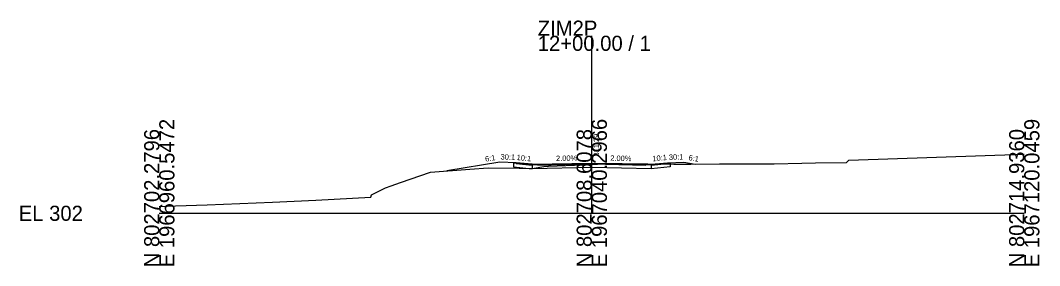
# Model space of a CAD drawing. Extents: x 1950845 to 1951408, y 736831 to 740365.
# Drawn here: x 1950844.5 to 1951033.1, y 738831.5 to 738876.9 of the extents above; entities that cross this region are included whole.
import ezdxf

# ---------------------------------------------------------------- set-up
doc = ezdxf.new("R2010")
doc.units = 0
for name, color, linetype in [('RD_GPK_XS_Cell', 7, 'Continuous'), ('RD_XS_Base', 7, 'Continuous'), ('RD_XS_EarthShd', 7, 'Continuous'), ('RD_XS_ExGround', 7, 'Continuous'), ('RD_XS_Pave', 7, 'Continuous'), ('RD_XS_PaveOvlay', 7, 'Continuous'), ('RD_XS_TieSlope', 7, 'Continuous'), ('RD_XS_TX_Elev_PR', 7, 'Continuous'), ('RD_XS_TX_Slope', 7, 'Continuous')]:
    doc.layers.add(name, color=color, linetype=linetype)

msp = doc.modelspace()

# ---------------------------------------------------------------- linework, layer by layer
at = {"layer": 'RD_GPK_XS_Cell'}
for p, q in [((1950950.22, 738841.19), (1950950.22, 738874.06)), ((1950870.22, 738841.19), (1950950.22, 738841.19)), ((1950950.22, 738841.19), (1951030.22, 738841.19))]:
    msp.add_line(p, q, dxfattribs=at)
at = {"layer": 'RD_XS_Base'}
for points in [[(1950939.22, 738850.1), (1950936.22, 738850.4), (1950935.72, 738850.45)], [(1950935.72, 738850.45), (1950935.72, 738849.79)], [(1950939.22, 738850.1), (1950939.22, 738849.44)], [(1950940.22, 738850.12), (1950950.22, 738850.32), (1950960.22, 738850.12)], [(1950961.22, 738850.1), (1950964.22, 738850.4), (1950964.72, 738850.45)], [(1950961.22, 738850.1), (1950961.22, 738849.44)], [(1950964.72, 738850.45), (1950964.72, 738849.79)], [(1950935.72, 738849.79), (1950939.22, 738849.44)], [(1950961.22, 738849.45), (1950950.22, 738849.66), (1950939.22, 738849.44)], [(1950964.72, 738849.79), (1950961.22, 738849.44)]]:
    msp.add_lwpolyline(points, dxfattribs=at)
at = {"layer": 'RD_XS_EarthShd'}
for points in [[(1950936.22, 738850.56), (1950933.22, 738850.66)], [(1950964.22, 738850.56), (1950967.22, 738850.66)]]:
    msp.add_lwpolyline(points, dxfattribs=at)
at = {"layer": 'RD_XS_ExGround'}
msp.add_lwpolyline([(1950870.22, 738842.43), (1950873.2, 738842.54), (1950879.08, 738842.76), (1950891.14, 738843.23), (1950899.18, 738843.62), (1950909.36, 738844.16), (1950909.46, 738844.61), (1950912.08, 738845.91), (1950913.1, 738846.28), (1950914.81, 738846.86), (1950920.37, 738848.79), (1950927.64, 738849.36), (1950931.05, 738849.63), (1950936.78, 738849.53), (1950939.19, 738849.46), (1950941.33, 738849.88), (1950942.19, 738849.9), (1950950.22, 738850.25), (1950953.38, 738850.39), (1950955.81, 738850.38), (1950965.39, 738850.29), (1950966.07, 738850.28), (1950967.09, 738850.29), (1950967.72, 738850.29), (1950968.52, 738850.3), (1950973.85, 738850.33), (1950974.26, 738850.33), (1950974.76, 738850.33), (1950975.5, 738850.33), (1950977.02, 738850.36), (1950982.21, 738850.36), (1950982.75, 738850.36), (1950983.96, 738850.36), (1950989.08, 738850.44), (1950991.6, 738850.5), (1950997.36, 738850.58), (1950997.74, 738851.04), (1951030.22, 738852.15)], dxfattribs=at)
at = {"layer": 'RD_XS_Pave'}
for points in [[(1950939.22, 738850.26), (1950936.22, 738850.56)], [(1950936.22, 738850.56), (1950936.22, 738850.4)], [(1950936.22, 738850.4), (1950939.22, 738850.1)], [(1950939.22, 738850.1), (1950939.22, 738850.26)], [(1950961.22, 738850.26), (1950964.22, 738850.56)], [(1950964.22, 738850.4), (1950961.22, 738850.1)], [(1950961.22, 738850.1), (1950961.22, 738850.26)], [(1950964.22, 738850.56), (1950964.22, 738850.4)]]:
    msp.add_lwpolyline(points, dxfattribs=at)
at = {"layer": 'RD_XS_PaveOvlay'}
for points in [[(1950939.22, 738850.26), (1950950.22, 738850.48), (1950961.22, 738850.26)], [(1950961.22, 738850.1), (1950950.22, 738850.32), (1950939.22, 738850.1)], [(1950939.22, 738850.26), (1950939.22, 738850.1)], [(1950961.22, 738850.26), (1950961.22, 738850.1)]]:
    msp.add_lwpolyline(points, dxfattribs=at)
at = {"layer": 'RD_XS_TieSlope'}
for points in [[(1950933.22, 738850.66), (1950923.43, 738849.03)], [(1950967.22, 738850.66), (1950969.34, 738850.31)]]:
    msp.add_lwpolyline(points, dxfattribs=at)

# ---------------------------------------------------------------- texts
at = {"layer": 'RD_GPK_XS_Cell'}
for s, p in [('ZIM2P', (1950940.22, 738874.06)), ('12+00.00 / 1', (1950940.22, 738871.26)), ('EL 302', (1950844.22, 738839.79))]:
    msp.add_text(s, height=2.8, dxfattribs=at).set_placement(p)
for s, p in [('E 1966960.5472', (1950873.02, 738831.19)), ('E 1967040.2966', (1950953.02, 738831.19)), ('E 1967120.0459', (1951033.02, 738831.19)), ('N 802702.2796', (1950870.22, 738831.19)), ('N 802708.6078', (1950950.22, 738831.19)), ('N 802714.9360', (1951030.22, 738831.19))]:
    msp.add_text(s, height=2.8, rotation=90, dxfattribs=at).set_placement(p)
at = {"layer": 'RD_XS_TX_Elev_PR'}
msp.add_text('311.29', height=1, rotation=90, dxfattribs=at).set_placement((1950951.57, 738851.69))
at = {"layer": 'RD_XS_TX_Slope'}
for s, rotation, p in [('6:1', 9.4642, (1950930.57, 738850.73)), ('30:1', 358.0908, (1950933.33, 738851.16)), ('10:1', 354.2894, (1950936.28, 738851.06)), ('2.00%', 1.1458, (1950943.61, 738850.85)), ('2.00%', 358.8542, (1950953.63, 738850.91)), ('10:1', 5.7106, (1950961.48, 738850.79)), ('30:1', 1.9092, (1950964.5, 738851.07)), ('6:1', 350.5358, (1950968.06, 738851.03))]:
    msp.add_text(s, height=1, rotation=rotation, dxfattribs=at).set_placement(p)

doc.saveas('drawing.dxf')
